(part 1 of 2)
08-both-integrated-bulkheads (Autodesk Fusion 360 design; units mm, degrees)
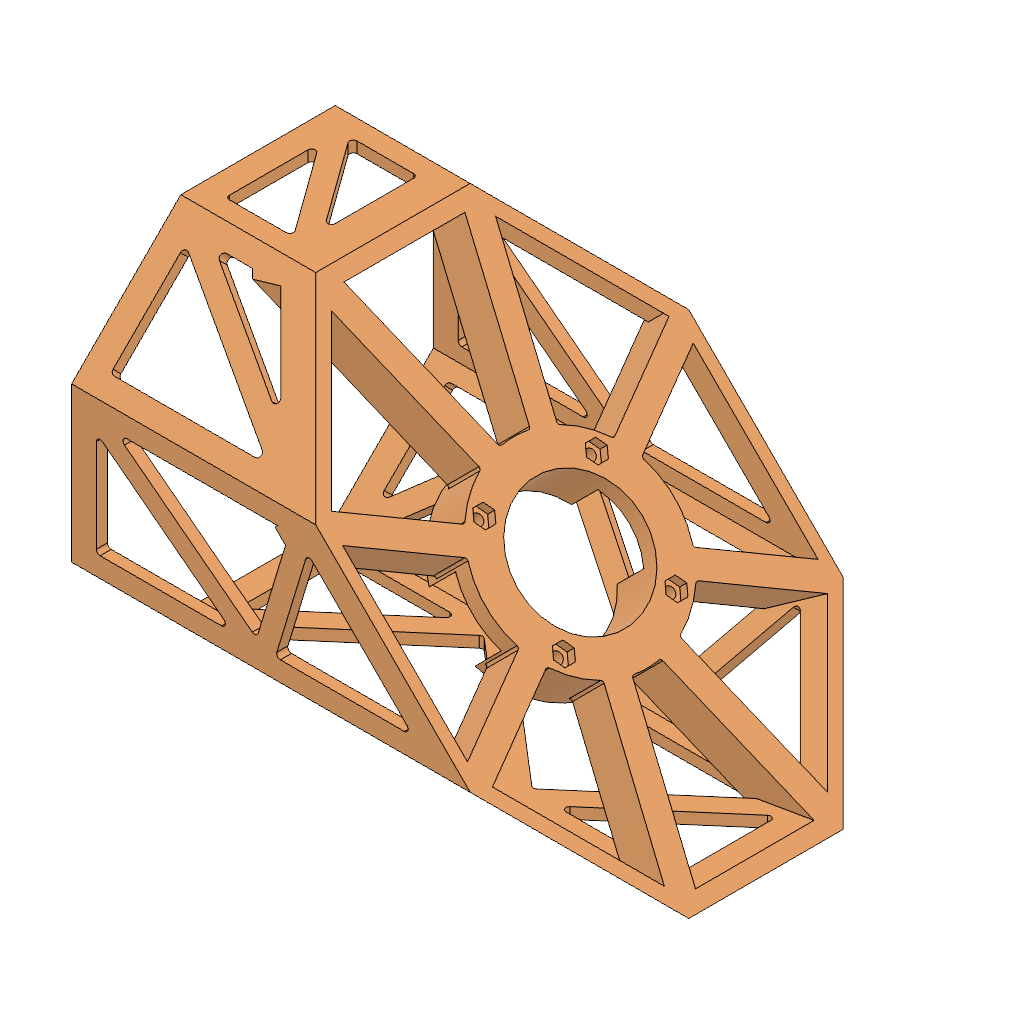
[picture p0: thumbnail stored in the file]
part number: 2026-11-02-20-17-55-344
part number: 2026-11-02-20-17-59-218
part number: 2026-11-02-20-17-59-224
parameter "bodyWidth" = 150 comment "Regular octagon across flats; corner diameter is larger."
parameter "bodyLength" = 260 comment "Overall straight length of the shared master blank."
parameter "splitAngle" = 45 comment "Keep this lesson angle at45 degrees."
parameter "faceGap" = 1 comment "Gap between the two printed joint faces."
parameter "wall" = 4.5 comment "Integrated shell and side brace radial thickness."
parameter "faceHalfWidth" = 31.066 (= "bodyWidth * ( sqrt(2) - 1 ) / 2") comment "Half-width of each outer planar facet."
parameter "memberWidth" = 8 comment "Nominal brace and corner chord width in a facet."
parameter "nodeHalfWidth" = 27.066 (= "faceHalfWidth - memberWidth / 2") comment "Chord centerlines measured from facet center."
parameter "jointNodeQ" = 7 comment "First truss skeleton row from the center joint plane."
parameter "endRim" = 10 comment "Uncut axial rim at each distant end."
parameter "endNodeX" = 124 (= "bodyLength / 2 - endRim + memberWidth / 2") comment "Last skeleton row before aperture inset."
parameter "apertureRadius" = 1.5 comment "Rounded internal corners at triangular openings."
parameter "spokeWidth" = 10 comment "Width of each deep bearing bulkhead spoke."
parameter "spokeDepth" = 18 comment "Bulkhead depth normal to the diagonal joint face."
parameter "carrierOD" = 52 comment "Outside of integrated A front bearing carrier."
parameter "rearCarrierClearance" = 46 comment "Internal carrier relief above front bearing shoulder."
parameter "tubeCornerChamfer" = 0.5 comment "Exposed outside octagon corner bevel."
parameter "tubeRimChamfer" = 0.3 comment "End rim and print-contact edge relief."
parameter "cordStation" = 125 (= "bodyLength / 2 - endRim / 2") comment "Load-test cord port center measured along body X."
parameter "bearingOD" = 22 comment "608 measured outside diameter."
parameter "bearingID" = 8 comment "608 bore."
parameter "bearingWidth" = 7 comment "608 width."
parameter "seatAllowance" = 0.2 comment "Trial DIAMETRAL clearance; choose with printed coupon."
parameter "seatDiameter" = 22.2 (= "bearingOD + seatAllowance") comment "Measured fit controls this."
parameter "coreOD" = 44 comment "Bearing holder outer diameter."
parameter "raceRelief" = 19.5 comment "Outer-ring shoulder opening; verify seals."
parameter "frontSeatDepth" = 7.1 comment "0.1 mm outer-ring axial allowance."
parameter "rearSeatDepth" = 7.2 comment "0.2 mm outer-ring axial float."
parameter "shoulder" = 3 comment "Backing behind each bearing seat."
parameter "supportSpacer" = 12 comment "Purchased metal M3 spacer length."
parameter "supportCircle" = 34 comment "Three M3 support bolts."
parameter "supportSpacerOD" = 6 comment "Purchased spacer outside diameter."
parameter "capThickness" = 3 comment "Both printed outer-ring retaining caps."
parameter "m3Clearance" = 3.3 comment "M3 through holes."
parameter "m4Clearance" = 4.3 comment "M4 through holes."
parameter "qFront" = 0.5 (= "faceGap / 2") comment "Front bearing starts at A mating face."
parameter "qFrontBack" = 10.6 (= "qFront + frontSeatDepth + shoulder") comment "End of integrated A holder."
parameter "qRearBase" = 22.6 (= "qFrontBack + supportSpacer") comment "Start of removable rear holder."
parameter "qRearBearing" = 25.6 (= "qRearBase + shoulder") comment "Rear bearing inner end."
parameter "qRearEnd" = 32.8 (= "qRearBearing + rearSeatDepth") comment "Rear holder outer end."
parameter "bearingSpacing" = 25.1 (= "qRearBearing - qFront") comment "Derived support-center spacing, not a bearing rating."
parameter "mountOD" = 76 comment "B mount and F flange outside diameter."
parameter "mountCircle" = 64 comment "Four M4 attachment holes."
parameter "mountOpening" = 50.3 comment "B through opening."
parameter "hubFace" = -23 comment "Metal hub flat mounting face."
parameter "adapterThickness" = 6 comment "F flange and metal compression sleeve length."
parameter "pilotDiameter" = 50 comment "F shallow centering pilot."
parameter "pilotInside" = 34 comment "Clearance around metal hub."
parameter "pilotHeight" = 2 comment "Short pilot only."
parameter "hubHoleSpacing" = 16 comment "Metal Sonic hub square hole spacing."
parameter "sleeveOD" = 8 comment "M4 metal compression sleeves."
parameter "sleeveAllowance" = 0.2 comment "Trial DIAMETRAL sleeve clearance."
parameter "shaftClearance" = 8.5 comment "F clearance hole; not a bearing."
parameter "nutAF" = 7.2 comment "M4 nominal 7 AF nut trial pocket."
parameter "nutDepth" = 4 comment "Open front M4 nut pocket."
parameter "rootRadius" = 1 comment "Hub-to-wall blend."
parameter "entryChamfer" = 0.4 comment "Assembly lead-in."
parameter "bedRelief" = 0.3 comment "Bed-contact edge allowance."
sketch "01 Master Octagon" plane through (0, 0, 0) normal (1, 0, 0) x axis (0, 0, -1)
  line L1 (31.066, 75) -> (75, 31.066)
  line L2 (-31.066, 75) -> (31.066, 75)
  line L3 (-75, 31.066) -> (-31.066, 75)
  line L4 (-75, -31.066) -> (-75, 31.066)
  line L5 (-31.066, -75) -> (-75, -31.066)
  line L6 (31.066, -75) -> (-31.066, -75)
  line L7 (75, -31.066) -> (31.066, -75)
  line L8 (75, 31.066) -> (75, -31.066)
  point P1 (0, 0)
  point P10 (0, 0)
  point P3 (31.066, 75)
  point P8 (31.066, -75)
  coincident P1 P10
  horizontal L2
  dimension "d59" distance P3 P8 = 150 (= "bodyWidth")
extrude "Extrude1" new body sketch "01 Master Octagon" distance 260 (= "bodyLength")
work_plane "WorkPlane1" RotateAngle 45 (= "splitAngle") ExtraOffset 0
split "Split1"
offset_faces "OffsetFaces1" distance -0.5 (= "-faceGap / 2")
offset_faces "OffsetFaces2" distance -0.5 (= "-faceGap / 2")
component_from_bodies "Body->Comp1"
component_from_bodies "Body->Comp2"
shell "Shell1" innerThickness 4.5 (= "wall")
shell "Shell1" innerThickness 4.5 (= "wall")
work_plane "WorkPlane1" RotateAngle -90 ExtraOffset 0
work_plane "WorkPlane2" AlongDistance 75 (= "bodyWidth / 2") ExtraOffset 0
sketch "A Facet 0 Triangle 1" plane through (0, 75, 0) normal (0, 1, 0) x axis (1, 0, 0)
  line L1 (-65.1005, -27.066) -> (-65.1005, 27.066)
  line L2 (60.9665, 27.066) -> (-65.1005, -27.066)
  line L3 (-65.1005, 27.066) -> (60.9665, 27.066)
  line L4 (-61.1005, -20.9953) -> (-61.1005, 23.066)
  line L5 (41.513, 23.066) -> (-61.1005, -20.9953)
  line L6 (-61.1005, 23.066) -> (41.513, 23.066)
  point P1 (0, 0)
  point P2 (-65.1005, 27.066)
  point P3 (-65.1005, -27.066)
  point P4 (60.9665, 27.066)
  dimension "d72" distance P1 P2 = 65.1005 (= "Linear Dimension-2")
  dimension "d73" distance P1 P2 = 27.066 (= "Linear Dimension-3")
  dimension "d74" distance P1 P3 = 65.1005 (= "Linear Dimension-4")
  dimension "d75" distance P1 P3 = 27.066 (= "Linear Dimension-5")
  dimension "d76" distance P1 P4 = 60.9665 (= "Linear Dimension-6")
  dimension "d77" distance P1 P4 = 27.066 (= "Linear Dimension-7")
  dimension "d78" = -4 (= "-memberWidth / 2")
extrude "Extrude1" cut sketch "A Facet 0 Triangle 1" profile of L5 L6 L4 against normal blind 4.7 (magnitude of "-( wall + 0.2 mm )")
sketch "A Facet 0 Triangle 2" plane through (0, 75, 0) normal (0, 1, 0) x axis (1, 0, 0)
  line L1 (60.9665, 27.066) -> (-65.1005, -27.066)
  line L2 (92.4832, -27.066) -> (60.9665, 27.066)
  line L3 (-65.1005, -27.066) -> (92.4832, -27.066)
  line L4 (59.2912, 21.9935) -> (-45.647, -23.066)
  line L5 (85.5258, -23.066) -> (59.2912, 21.9935)
  line L6 (-45.647, -23.066) -> (85.5258, -23.066)
  point P1 (0, 0)
  point P2 (-65.1005, -27.066)
  point P3 (60.9665, 27.066)
  point P4 (92.4832, -27.066)
  dimension "d81" distance P1 P2 = 65.1005 (= "Linear Dimension-2")
  dimension "d82" distance P1 P2 = 27.066 (= "Linear Dimension-3")
  dimension "d83" distance P1 P3 = 60.9665 (= "Linear Dimension-4")
  dimension "d84" distance P1 P3 = 27.066 (= "Linear Dimension-5")
  dimension "d85" distance P1 P4 = 92.4832 (= "Linear Dimension-6")
  dimension "d86" distance P1 P4 = 27.066 (= "Linear Dimension-7")
  dimension "d87" = 4 (= "memberWidth / 2")
extrude "Extrude2" cut sketch "A Facet 0 Triangle 2" profile of L5 L6 L4 against normal blind 4.7 (magnitude of "-( wall + 0.2 mm )")
sketch "A Facet 0 Triangle 3" plane through (0, 75, 0) normal (0, 1, 0) x axis (1, 0, 0)
  line L1 (92.4832, -27.066) -> (60.9665, 27.066)
  line L2 (124, 27.066) -> (92.4832, -27.066)
  line L3 (60.9665, 27.066) -> (124, 27.066)
  line L4 (92.4832, -19.1161) -> (67.924, 23.066)
  line L5 (117.0425, 23.066) -> (92.4832, -19.1161)
  line L6 (67.924, 23.066) -> (117.0425, 23.066)
  point P1 (0, 0)
  point P2 (60.9665, 27.066)
  point P3 (92.4832, -27.066)
  point P4 (124, 27.066)
  dimension "d90" distance P1 P2 = 60.9665 (= "Linear Dimension-2")
  dimension "d91" distance P1 P2 = 27.066 (= "Linear Dimension-3")
  dimension "d92" distance P1 P3 = 92.4832 (= "Linear Dimension-4")
  dimension "d93" distance P1 P3 = 27.066 (= "Linear Dimension-5")
  dimension "d94" distance P1 P4 = 124 (= "Linear Dimension-6")
  dimension "d95" distance P1 P4 = 27.066 (= "Linear Dimension-7")
  dimension "d96" = -4 (= "-memberWidth / 2")
extrude "Extrude3" cut sketch "A Facet 0 Triangle 3" profile of L5 L6 L4 against normal blind 4.7 (magnitude of "-( wall + 0.2 mm )")
sketch "A Facet 0 Triangle 4" plane through (0, 75, 0) normal (0, 1, 0) x axis (1, 0, 0)
  line L1 (124, 27.066) -> (92.4832, -27.066)
  line L2 (124, -27.066) -> (124, 27.066)
  line L3 (92.4832, -27.066) -> (124, -27.066)
  line L4 (120, 12.2459) -> (99.4407, -23.066)
  line L5 (120, -23.066) -> (120, 12.2459)
  line L6 (99.4407, -23.066) -> (120, -23.066)
  point P1 (0, 0)
  point P2 (92.4832, -27.066)
  point P3 (124, 27.066)
  point P4 (124, -27.066)
  dimension "d99" distance P1 P2 = 92.4832 (= "Linear Dimension-2")
  dimension "d100" distance P1 P2 = 27.066 (= "Linear Dimension-3")
  dimension "d101" distance P1 P3 = 124 (= "Linear Dimension-4")
  dimension "d102" distance P1 P3 = 27.066 (= "Linear Dimension-5")
  dimension "d103" distance P1 P4 = 124 (= "Linear Dimension-6")
  dimension "d104" distance P1 P4 = 27.066 (= "Linear Dimension-7")
  dimension "d105" = 4 (= "memberWidth / 2")
extrude "Extrude4" cut sketch "A Facet 0 Triangle 4" profile of L5 L6 L4 against normal blind 4.7 (magnitude of "-( wall + 0.2 mm )")
fillet "Fillet1" radius 1.5 (= "apertureRadius")
work_plane "WorkPlane3" RotateAngle -45 ExtraOffset 0
work_plane "WorkPlane4" AlongDistance 75 (= "bodyWidth / 2") ExtraOffset 0
sketch "A Facet 45 Triangle 1" plane through (0, 53.033, 53.033) normal (0, 0.7071, 0.7071) x axis (1, 0, 0)
  line L1 (-23.9949, -27.066) -> (-62.2721, 27.066)
  line L2 (-0.1814, 27.066) -> (-23.9949, -27.066)
  line L3 (-62.2721, 27.066) -> (-0.1814, 27.066)
  line L4 (-24.81, -18.9852) -> (-54.5447, 23.066)
  line L5 (-6.311, 23.066) -> (-24.81, -18.9852)
  line L6 (-54.5447, 23.066) -> (-6.311, 23.066)
  point P1 (0, 0)
  point P2 (-62.2721, 27.066)
  point P3 (-23.9949, -27.066)
  point P4 (-0.1814, 27.066)
  dimension "d114" distance P1 P2 = 62.2721 (= "Linear Dimension-2")
  dimension "d115" distance P1 P2 = 27.066 (= "Linear Dimension-3")
  dimension "d116" distance P1 P3 = 23.9949 (= "Linear Dimension-4")
  dimension "d117" distance P1 P3 = 27.066 (= "Linear Dimension-5")
  dimension "d118" distance P1 P4 = 0.1814 (= "Linear Dimension-6")
  dimension "d119" distance P1 P4 = 27.066 (= "Linear Dimension-7")
  dimension "d120" = -4 (= "-memberWidth / 2")
extrude "Extrude5" cut sketch "A Facet 45 Triangle 1" profile of L5 L6 L4 against normal blind 4.7 (magnitude of "-( wall + 0.2 mm )")
sketch "A Facet 45 Triangle 2" plane through (0, 53.033, 53.033) normal (0, 0.7071, 0.7071) x axis (1, 0, 0)
  line L1 (-0.1814, 27.066) -> (-23.9949, -27.066)
  line L2 (74.6684, -27.066) -> (-0.1814, 27.066)
  line L3 (-23.9949, -27.066) -> (74.6684, -27.066)
  line L4 (1.4863, 20.9235) -> (-17.8653, -23.066)
  line L5 (62.3117, -23.066) -> (1.4863, 20.9235)
  line L6 (-17.8653, -23.066) -> (62.3117, -23.066)
  point P1 (0, 0)
  point P2 (-23.9949, -27.066)
  point P3 (-0.1814, 27.066)
  point P4 (74.6684, -27.066)
  dimension "d123" distance P1 P2 = 23.9949 (= "Linear Dimension-2")
  dimension "d124" distance P1 P2 = 27.066 (= "Linear Dimension-3")
  dimension "d125" distance P1 P3 = 0.1814 (= "Linear Dimension-4")
  dimension "d126" distance P1 P3 = 27.066 (= "Linear Dimension-5")
  dimension "d127" distance P1 P4 = 74.6684 (= "Linear Dimension-6")
  dimension "d128" distance P1 P4 = 27.066 (= "Linear Dimension-7")
  dimension "d129" = 4 (= "memberWidth / 2")
extrude "Extrude6" cut sketch "A Facet 45 Triangle 2" profile of L5 L6 L4 against normal blind 4.7 (magnitude of "-( wall + 0.2 mm )")
sketch "A Facet 45 Triangle 3" plane through (0, 53.033, 53.033) normal (0, 0.7071, 0.7071) x axis (1, 0, 0)
  line L1 (74.6684, -27.066) -> (-0.1814, 27.066)
  line L2 (124, 27.066) -> (74.6684, -27.066)
  line L3 (-0.1814, 27.066) -> (124, 27.066)
  line L4 (74.1179, -21.7315) -> (12.1753, 23.066)
  line L5 (114.9429, 23.066) -> (74.1179, -21.7315)
  line L6 (12.1753, 23.066) -> (114.9429, 23.066)
  point P1 (0, 0)
  point P2 (-0.1814, 27.066)
  point P3 (74.6684, -27.066)
  point P4 (124, 27.066)
  dimension "d132" distance P1 P2 = 0.1814 (= "Linear Dimension-2")
  dimension "d133" distance P1 P2 = 27.066 (= "Linear Dimension-3")
  dimension "d134" distance P1 P3 = 74.6684 (= "Linear Dimension-4")
  dimension "d135" distance P1 P3 = 27.066 (= "Linear Dimension-5")
  dimension "d136" distance P1 P4 = 124 (= "Linear Dimension-6")
  dimension "d137" distance P1 P4 = 27.066 (= "Linear Dimension-7")
  dimension "d138" = -4 (= "-memberWidth / 2")
extrude "Extrude7" cut sketch "A Facet 45 Triangle 3" profile of L5 L6 L4 against normal blind 4.7 (magnitude of "-( wall + 0.2 mm )")
sketch "A Facet 45 Triangle 4" plane through (0, 53.033, 53.033) normal (0, 0.7071, 0.7071) x axis (1, 0, 0)
  line L1 (124, 27.066) -> (74.6684, -27.066)
  line L2 (124, -27.066) -> (124, 27.066)
  line L3 (74.6684, -27.066) -> (124, -27.066)
  line L4 (120, 16.7383) -> (83.7255, -23.066)
  line L5 (120, -23.066) -> (120, 16.7383)
  line L6 (83.7255, -23.066) -> (120, -23.066)
  point P1 (0, 0)
  point P2 (74.6684, -27.066)
  point P3 (124, 27.066)
  point P4 (124, -27.066)
  dimension "d141" distance P1 P2 = 74.6684 (= "Linear Dimension-2")
  dimension "d142" distance P1 P2 = 27.066 (= "Linear Dimension-3")
  dimension "d143" distance P1 P3 = 124 (= "Linear Dimension-4")
  dimension "d144" distance P1 P3 = 27.066 (= "Linear Dimension-5")
  dimension "d145" distance P1 P4 = 124 (= "Linear Dimension-6")
  dimension "d146" distance P1 P4 = 27.066 (= "Linear Dimension-7")
  dimension "d147" = 4 (= "memberWidth / 2")
extrude "Extrude8" cut sketch "A Facet 45 Triangle 4" profile of L5 L6 L4 against normal blind 4.7 (magnitude of "-( wall + 0.2 mm )")
fillet "Fillet2" radius 1.5 (= "apertureRadius")
work_plane "WorkPlane5" RotateAngle 0 ExtraOffset 0
work_plane "WorkPlane6" AlongDistance 75 (= "bodyWidth / 2") ExtraOffset 0
sketch "A Facet 90 Triangle 1" plane through (0, 0, 75) normal (0, 0, 1) x axis (1, 0, 0)
  line L1 (36.9655, -27.066) -> (-17.1665, 27.066)
  line L2 (53.4167, 27.066) -> (36.9655, -27.066)
  line L3 (-17.1665, 27.066) -> (53.4167, 27.066)
  line L4 (35.0777, -19.5214) -> (-7.5097, 23.066)
  line L5 (48.0205, 23.066) -> (35.0777, -19.5214)
  line L6 (-7.5097, 23.066) -> (48.0205, 23.066)
  point P1 (0, 0)
  point P2 (-17.1665, 27.066)
  point P3 (36.9655, -27.066)
  point P4 (53.4167, 27.066)
  dimension "d156" distance P1 P2 = 17.1665 (= "Linear Dimension-2")
  dimension "d157" distance P1 P2 = 27.066 (= "Linear Dimension-3")
  dimension "d158" distance P1 P3 = 36.9655 (= "Linear Dimension-4")
  dimension "d159" distance P1 P3 = 27.066 (= "Linear Dimension-5")
  dimension "d160" distance P1 P4 = 53.4167 (= "Linear Dimension-6")
  dimension "d161" distance P1 P4 = 27.066 (= "Linear Dimension-7")
  dimension "d162" = -4 (= "-memberWidth / 2")
extrude "Extrude9" cut sketch "A Facet 90 Triangle 1" profile of L5 L6 L4 against normal blind 4.7 (magnitude of "-( wall + 0.2 mm )")
sketch "A Facet 90 Triangle 2" plane through (0, 0, 75) normal (0, 0, 1) x axis (1, 0, 0)
  line L1 (53.4167, 27.066) -> (36.9655, -27.066)
  line L2 (124, -27.066) -> (53.4167, 27.066)
  line L3 (36.9655, -27.066) -> (124, -27.066)
  line L4 (55.5648, 20.3777) -> (42.3618, -23.066)
  line L5 (112.2115, -23.066) -> (55.5648, 20.3777)
  line L6 (42.3618, -23.066) -> (112.2115, -23.066)
  point P1 (0, 0)
  point P2 (36.9655, -27.066)
  point P3 (53.4167, 27.066)
  point P4 (124, -27.066)
  dimension "d165" distance P1 P2 = 36.9655 (= "Linear Dimension-2")
  dimension "d166" distance P1 P2 = 27.066 (= "Linear Dimension-3")
  dimension "d167" distance P1 P3 = 53.4167 (= "Linear Dimension-4")
  dimension "d168" distance P1 P3 = 27.066 (= "Linear Dimension-5")
  dimension "d169" distance P1 P4 = 124 (= "Linear Dimension-6")
  dimension "d170" distance P1 P4 = 27.066 (= "Linear Dimension-7")
  dimension "d171" = 4 (= "memberWidth / 2")
extrude "Extrude10" cut sketch "A Facet 90 Triangle 2" profile of L5 L6 L4 against normal blind 4.7 (magnitude of "-( wall + 0.2 mm )")
sketch "A Facet 90 Triangle 3" plane through (0, 0, 75) normal (0, 0, 1) x axis (1, 0, 0)
  line L1 (124, -27.066) -> (53.4167, 27.066)
  line L2 (124, 27.066) -> (124, -27.066)
  line L3 (53.4167, 27.066) -> (124, 27.066)
  line L4 (120, -18.9574) -> (65.2053, 23.066)
  line L5 (120, 23.066) -> (120, -18.9574)
  line L6 (65.2053, 23.066) -> (120, 23.066)
  point P1 (0, 0)
  point P2 (53.4167, 27.066)
  point P3 (124, -27.066)
  point P4 (124, 27.066)
  dimension "d174" distance P1 P2 = 53.4167 (= "Linear Dimension-2")
  dimension "d175" distance P1 P2 = 27.066 (= "Linear Dimension-3")
  dimension "d176" distance P1 P3 = 124 (= "Linear Dimension-4")
  dimension "d177" distance P1 P3 = 27.066 (= "Linear Dimension-5")
  dimension "d178" distance P1 P4 = 124 (= "Linear Dimension-6")
  dimension "d179" distance P1 P4 = 27.066 (= "Linear Dimension-7")
  dimension "d180" = -4 (= "-memberWidth / 2")
extrude "Extrude11" cut sketch "A Facet 90 Triangle 3" profile of L5 L6 L4 against normal blind 4.7 (magnitude of "-( wall + 0.2 mm )")
fillet "Fillet3" radius 1.5 (= "apertureRadius")
work_plane "WorkPlane7" RotateAngle 45 ExtraOffset 0
work_plane "WorkPlane8" AlongDistance 75 (= "bodyWidth / 2") ExtraOffset 0
sketch "A Facet 135 Triangle 1" plane through (0, -53.033, 53.033) normal (0, -0.7071, 0.7071) x axis (1, 0, 0)
  line L1 (82.0711, -27.066) -> (43.7939, 27.066)
  line L2 (124, 27.066) -> (82.0711, -27.066)
  line L3 (43.7939, 27.066) -> (124, 27.066)
  line L4 (82.2175, -20.3449) -> (51.5213, 23.066)
  line L5 (115.8422, 23.066) -> (82.2175, -20.3449)
  line L6 (51.5213, 23.066) -> (115.8422, 23.066)
  point P1 (0, 0)
  point P2 (43.7939, 27.066)
  point P3 (82.0711, -27.066)
  point P4 (124, 27.066)
  dimension "d189" distance P1 P2 = 43.7939 (= "Linear Dimension-2")
  dimension "d190" distance P1 P2 = 27.066 (= "Linear Dimension-3")
  dimension "d191" distance P1 P3 = 82.0711 (= "Linear Dimension-4")
  dimension "d192" distance P1 P3 = 27.066 (= "Linear Dimension-5")
  dimension "d193" distance P1 P4 = 124 (= "Linear Dimension-6")
  dimension "d194" distance P1 P4 = 27.066 (= "Linear Dimension-7")
  dimension "d195" = -4 (= "-memberWidth / 2")
extrude "Extrude12" cut sketch "A Facet 135 Triangle 1" profile of L5 L6 L4 against normal blind 4.7 (magnitude of "-( wall + 0.2 mm )")
sketch "A Facet 135 Triangle 2" plane through (0, -53.033, 53.033) normal (0, -0.7071, 0.7071) x axis (1, 0, 0)
  line L1 (124, 27.066) -> (82.0711, -27.066)
  line L2 (124, -27.066) -> (124, 27.066)
  line L3 (82.0711, -27.066) -> (124, -27.066)
  line L4 (120, 15.3697) -> (90.2289, -23.066)
  line L5 (120, -23.066) -> (120, 15.3697)
  line L6 (90.2289, -23.066) -> (120, -23.066)
  point P1 (0, 0)
  point P2 (82.0711, -27.066)
  point P3 (124, 27.066)
  point P4 (124, -27.066)
  dimension "d198" distance P1 P2 = 82.0711 (= "Linear Dimension-2")
  dimension "d199" distance P1 P2 = 27.066 (= "Linear Dimension-3")
  dimension "d200" distance P1 P3 = 124 (= "Linear Dimension-4")
  dimension "d201" distance P1 P3 = 27.066 (= "Linear Dimension-5")
  dimension "d202" distance P1 P4 = 124 (= "Linear Dimension-6")
  dimension "d203" distance P1 P4 = 27.066 (= "Linear Dimension-7")
  dimension "d204" = 4 (= "memberWidth / 2")
extrude "Extrude13" cut sketch "A Facet 135 Triangle 2" profile of L5 L6 L4 against normal blind 4.7 (magnitude of "-( wall + 0.2 mm )")
fillet "Fillet4" radius 1.5 (= "apertureRadius")
work_plane "WorkPlane9" RotateAngle 90 ExtraOffset 0
work_plane "WorkPlane10" AlongDistance 75 (= "bodyWidth / 2") ExtraOffset 0
sketch "A Facet 180 Triangle 1" plane through (0, -75, 0) normal (0, -1, 0) x axis (-1, 0, 0)
  line L1 (-84.8995, 27.066) -> (-84.8995, -27.066)
  line L2 (-124, -27.066) -> (-84.8995, 27.066)
  line L3 (-84.8995, -27.066) -> (-124, -27.066)
  line L4 (-88.8995, 14.697) -> (-88.8995, -23.066)
  line L5 (-116.1764, -23.066) -> (-88.8995, 14.697)
  line L6 (-88.8995, -23.066) -> (-116.1764, -23.066)
  point P1 (0, 0)
  point P2 (-84.8995, -27.066)
  point P3 (-84.8995, 27.066)
  point P4 (-124, -27.066)
  dimension "d213" distance P1 P2 = 84.8995 (= "Linear Dimension-2")
  dimension "d214" distance P1 P2 = 27.066 (= "Linear Dimension-3")
  dimension "d215" distance P1 P3 = 84.8995 (= "Linear Dimension-4")
  dimension "d216" distance P1 P3 = 27.066 (= "Linear Dimension-5")
  dimension "d217" distance P1 P4 = 124 (= "Linear Dimension-6")
  dimension "d218" distance P1 P4 = 27.066 (= "Linear Dimension-7")
  dimension "d219" = -4 (= "-memberWidth / 2")
extrude "Extrude14" cut sketch "A Facet 180 Triangle 1" profile of L5 L6 L4 against normal blind 4.7 (magnitude of "-( wall + 0.2 mm )")
sketch "A Facet 180 Triangle 2" plane through (0, -75, 0) normal (0, -1, 0) x axis (-1, 0, 0)
  line L1 (-124, -27.066) -> (-84.8995, 27.066)
  line L2 (-124, 27.066) -> (-124, -27.066)
  line L3 (-84.8995, 27.066) -> (-124, 27.066)
  line L4 (-120, -14.697) -> (-92.7231, 23.066)
  line L5 (-120, 23.066) -> (-120, -14.697)
  line L6 (-92.7231, 23.066) -> (-120, 23.066)
  point P1 (0, 0)
  point P2 (-84.8995, 27.066)
  point P3 (-124, -27.066)
  point P4 (-124, 27.066)
  dimension "d222" distance P1 P2 = 84.8995 (= "Linear Dimension-2")
  dimension "d223" distance P1 P2 = 27.066 (= "Linear Dimension-3")
  dimension "d224" distance P1 P3 = 124 (= "Linear Dimension-4")
  dimension "d225" distance P1 P3 = 27.066 (= "Linear Dimension-5")
  dimension "d226" distance P1 P4 = 124 (= "Linear Dimension-6")
  dimension "d227" distance P1 P4 = 27.066 (= "Linear Dimension-7")
  dimension "d228" = 4 (= "memberWidth / 2")
extrude "Extrude15" cut sketch "A Facet 180 Triangle 2" profile of L5 L6 L4 against normal blind 4.7 (magnitude of "-( wall + 0.2 mm )")
fillet "Fillet5" radius 1.5 (= "apertureRadius")
work_plane "WorkPlane11" RotateAngle 135 ExtraOffset 0
work_plane "WorkPlane12" AlongDistance 75 (= "bodyWidth / 2") ExtraOffset 0
sketch "A Facet 225 Triangle 1" plane through (0, -53.033, -53.033) normal (0, -0.7071, -0.7071) x axis (1, 0, 0)
  line L1 (43.7939, -27.066) -> (82.0711, 27.066)
  line L2 (124, 27.066) -> (43.7939, -27.066)
  line L3 (82.0711, 27.066) -> (124, 27.066)
  line L4 (59.6927, -11.51) -> (84.1416, 23.066)
  line L5 (110.9231, 23.066) -> (59.6927, -11.51)
  line L6 (84.1416, 23.066) -> (110.9231, 23.066)
  point P1 (0, 0)
  point P2 (82.0711, 27.066)
  point P3 (43.7939, -27.066)
  point P4 (124, 27.066)
  dimension "d237" distance P1 P2 = 82.0711 (= "Linear Dimension-2")
  dimension "d238" distance P1 P2 = 27.066 (= "Linear Dimension-3")
  dimension "d239" distance P1 P3 = 43.7939 (= "Linear Dimension-4")
  dimension "d240" distance P1 P3 = 27.066 (= "Linear Dimension-5")
  dimension "d241" distance P1 P4 = 124 (= "Linear Dimension-6")
  dimension "d242" distance P1 P4 = 27.066 (= "Linear Dimension-7")
  dimension "d243" = -4 (= "-memberWidth / 2")
extrude "Extrude16" cut sketch "A Facet 225 Triangle 1" profile of L5 L6 L4 against normal blind 4.7 (magnitude of "-( wall + 0.2 mm )")
sketch "A Facet 225 Triangle 2" plane through (0, -53.033, -53.033) normal (0, -0.7071, -0.7071) x axis (1, 0, 0)
  line L1 (124, 27.066) -> (43.7939, -27.066)
  line L2 (124, -27.066) -> (124, 27.066)
  line L3 (43.7939, -27.066) -> (124, -27.066)
  line L4 (120, 19.5406) -> (56.8709, -23.066)
  line L5 (120, -23.066) -> (120, 19.5406)
  line L6 (56.8709, -23.066) -> (120, -23.066)
  point P1 (0, 0)
  point P2 (43.7939, -27.066)
  point P3 (124, 27.066)
  point P4 (124, -27.066)
  dimension "d246" distance P1 P2 = 43.7939 (= "Linear Dimension-2")
  dimension "d247" distance P1 P2 = 27.066 (= "Linear Dimension-3")
  dimension "d248" distance P1 P3 = 124 (= "Linear Dimension-4")
  dimension "d249" distance P1 P3 = 27.066 (= "Linear Dimension-5")
  dimension "d250" distance P1 P4 = 124 (= "Linear Dimension-6")
  dimension "d251" distance P1 P4 = 27.066 (= "Linear Dimension-7")
  dimension "d252" = 4 (= "memberWidth / 2")
extrude "Extrude17" cut sketch "A Facet 225 Triangle 2" profile of L5 L6 L4 against normal blind 4.7 (magnitude of "-( wall + 0.2 mm )")
fillet "Fillet6" radius 1.5 (= "apertureRadius")
work_plane "WorkPlane13" RotateAngle 180 ExtraOffset 0
work_plane "WorkPlane14" AlongDistance 75 (= "bodyWidth / 2") ExtraOffset 0
sketch "A Facet 270 Triangle 1" plane through (0, 0, -75) normal (0, 0, -1) x axis (-1, 0, 0)
  line L1 (17.1665, 27.066) -> (-36.9655, -27.066)
  line L2 (-80.4828, -27.066) -> (17.1665, 27.066)
  line L3 (-36.9655, -27.066) -> (-80.4828, -27.066)
  line L4 (-5.7896, 9.7668) -> (-38.6224, -23.066)
  line L5 (-65.0169, -23.066) -> (-5.7896, 9.7668)
  line L6 (-38.6224, -23.066) -> (-65.0169, -23.066)
  point P1 (0, 0)
  point P2 (-36.9655, -27.066)
  point P3 (17.1665, 27.066)
  point P4 (-80.4828, -27.066)
  dimension "d261" distance P1 P2 = 36.9655 (= "Linear Dimension-2")
  dimension "d262" distance P1 P2 = 27.066 (= "Linear Dimension-3")
  dimension "d263" distance P1 P3 = 17.1665 (= "Linear Dimension-4")
  dimension "d264" distance P1 P3 = 27.066 (= "Linear Dimension-5")
  dimension "d265" distance P1 P4 = 80.4828 (= "Linear Dimension-6")
  dimension "d266" distance P1 P4 = 27.066 (= "Linear Dimension-7")
  dimension "d267" = -4 (= "-memberWidth / 2")
extrude "Extrude18" cut sketch "A Facet 270 Triangle 1" profile of L5 L6 L4 against normal blind 4.7 (magnitude of "-( wall + 0.2 mm )")
sketch "A Facet 270 Triangle 2" plane through (0, 0, -75) normal (0, 0, -1) x axis (-1, 0, 0)
  line L1 (-80.4828, -27.066) -> (17.1665, 27.066)
  line L2 (-124, 27.066) -> (-80.4828, -27.066)
  line L3 (17.1665, 27.066) -> (-124, 27.066)
  line L4 (-79.4759, -21.9343) -> (1.7007, 23.066)
  line L5 (-115.6521, 23.066) -> (-79.4759, -21.9343)
  line L6 (1.7007, 23.066) -> (-115.6521, 23.066)
  point P1 (0, 0)
  point P2 (17.1665, 27.066)
  point P3 (-80.4828, -27.066)
  point P4 (-124, 27.066)
  dimension "d270" distance P1 P2 = 17.1665 (= "Linear Dimension-2")
  dimension "d271" distance P1 P2 = 27.066 (= "Linear Dimension-3")
  dimension "d272" distance P1 P3 = 80.4828 (= "Linear Dimension-4")
  dimension "d273" distance P1 P3 = 27.066 (= "Linear Dimension-5")
  dimension "d274" distance P1 P4 = 124 (= "Linear Dimension-6")
  dimension "d275" distance P1 P4 = 27.066 (= "Linear Dimension-7")
  dimension "d276" = 4 (= "memberWidth / 2")
extrude "Extrude19" cut sketch "A Facet 270 Triangle 2" profile of L5 L6 L4 against normal blind 4.7 (magnitude of "-( wall + 0.2 mm )")
sketch "A Facet 270 Triangle 3" plane through (0, 0, -75) normal (0, 0, -1) x axis (-1, 0, 0)
  line L1 (-124, 27.066) -> (-80.4828, -27.066)
  line L2 (-124, -27.066) -> (-124, 27.066)
  line L3 (-80.4828, -27.066) -> (-124, -27.066)
  line L4 (-120, 15.7062) -> (-88.8307, -23.066)
  line L5 (-120, -23.066) -> (-120, 15.7062)
  line L6 (-88.8307, -23.066) -> (-120, -23.066)
  point P1 (0, 0)
  point P2 (-80.4828, -27.066)
  point P3 (-124, 27.066)
  point P4 (-124, -27.066)
  dimension "d279" distance P1 P2 = 80.4828 (= "Linear Dimension-2")
  dimension "d280" distance P1 P2 = 27.066 (= "Linear Dimension-3")
  dimension "d281" distance P1 P3 = 124 (= "Linear Dimension-4")
  dimension "d282" distance P1 P3 = 27.066 (= "Linear Dimension-5")
  dimension "d283" distance P1 P4 = 124 (= "Linear Dimension-6")
  dimension "d284" distance P1 P4 = 27.066 (= "Linear Dimension-7")
  dimension "d285" = -4 (= "-memberWidth / 2")
extrude "Extrude20" cut sketch "A Facet 270 Triangle 3" profile of L5 L6 L4 against normal blind 4.7 (magnitude of "-( wall + 0.2 mm )")
fillet "Fillet7" radius 1.5 (= "apertureRadius")
work_plane "WorkPlane15" RotateAngle 225 ExtraOffset 0
work_plane "WorkPlane16" AlongDistance 75 (= "bodyWidth / 2") ExtraOffset 0
sketch "A Facet 315 Triangle 1" plane through (0, 53.033, -53.033) normal (0, 0.7071, -0.7071) x axis (1, 0, 0)
  line L1 (-62.2721, -27.066) -> (-23.9949, 27.066)
  line L2 (25.3367, 27.066) -> (-62.2721, -27.066)
  line L3 (-23.9949, 27.066) -> (25.3367, 27.066)
  line L4 (-47.6674, -13.34) -> (-21.9244, 23.066)
  line L5 (11.2532, 23.066) -> (-47.6674, -13.34)
  line L6 (-21.9244, 23.066) -> (11.2532, 23.066)
  point P1 (0, 0)
  point P2 (-23.9949, 27.066)
  point P3 (-62.2721, -27.066)
  point P4 (25.3367, 27.066)
  dimension "d294" distance P1 P2 = 23.9949 (= "Linear Dimension-2")
  dimension "d295" distance P1 P2 = 27.066 (= "Linear Dimension-3")
  dimension "d296" distance P1 P3 = 62.2721 (= "Linear Dimension-4")
  dimension "d297" distance P1 P3 = 27.066 (= "Linear Dimension-5")
  dimension "d298" distance P1 P4 = 25.3367 (= "Linear Dimension-6")
  dimension "d299" distance P1 P4 = 27.066 (= "Linear Dimension-7")
  dimension "d300" = -4 (= "-memberWidth / 2")
extrude "Extrude21" cut sketch "A Facet 315 Triangle 1" profile of L5 L6 L4 against normal blind 4.7 (magnitude of "-( wall + 0.2 mm )")
sketch "A Facet 315 Triangle 2" plane through (0, 53.033, -53.033) normal (0, 0.7071, -0.7071) x axis (1, 0, 0)
  line L1 (25.3367, 27.066) -> (-62.2721, -27.066)
  line L2 (61.9093, -27.066) -> (25.3367, 27.066)
  line L3 (-62.2721, -27.066) -> (61.9093, -27.066)
  line L4 (24.1722, 21.6445) -> (-48.1886, -23.066)
  line L5 (54.3795, -23.066) -> (24.1722, 21.6445)
  line L6 (-48.1886, -23.066) -> (54.3795, -23.066)
  point P1 (0, 0)
  point P2 (-62.2721, -27.066)
  point P3 (25.3367, 27.066)
  point P4 (61.9093, -27.066)
  dimension "d303" distance P1 P2 = 62.2721 (= "Linear Dimension-2")
  dimension "d304" distance P1 P2 = 27.066 (= "Linear Dimension-3")
  dimension "d305" distance P1 P3 = 25.3367 (= "Linear Dimension-4")
  dimension "d306" distance P1 P3 = 27.066 (= "Linear Dimension-5")
  dimension "d307" distance P1 P4 = 61.9093 (= "Linear Dimension-6")
  dimension "d308" distance P1 P4 = 27.066 (= "Linear Dimension-7")
  dimension "d309" = 4 (= "memberWidth / 2")
extrude "Extrude22" cut sketch "A Facet 315 Triangle 2" profile of L5 L6 L4 against normal blind 4.7 (magnitude of "-( wall + 0.2 mm )")
sketch "A Facet 315 Triangle 3" plane through (0, 53.033, -53.033) normal (0, 0.7071, -0.7071) x axis (1, 0, 0)
  line L1 (61.9093, -27.066) -> (25.3367, 27.066)
  line L2 (124, 27.066) -> (61.9093, -27.066)
  line L3 (25.3367, 27.066) -> (124, 27.066)
  line L4 (62.6909, -21.0779) -> (32.8665, 23.066)
  line L5 (113.325, 23.066) -> (62.6909, -21.0779)
  line L6 (32.8665, 23.066) -> (113.325, 23.066)
  point P1 (0, 0)
  point P2 (25.3367, 27.066)
  point P3 (61.9093, -27.066)
  point P4 (124, 27.066)
  dimension "d312" distance P1 P2 = 25.3367 (= "Linear Dimension-2")
  dimension "d313" distance P1 P2 = 27.066 (= "Linear Dimension-3")
  dimension "d314" distance P1 P3 = 61.9093 (= "Linear Dimension-4")
  dimension "d315" distance P1 P3 = 27.066 (= "Linear Dimension-5")
  dimension "d316" distance P1 P4 = 124 (= "Linear Dimension-6")
  dimension "d317" distance P1 P4 = 27.066 (= "Linear Dimension-7")
  dimension "d318" = -4 (= "-memberWidth / 2")
extrude "Extrude23" cut sketch "A Facet 315 Triangle 3" profile of L5 L6 L4 against normal blind 4.7 (magnitude of "-( wall + 0.2 mm )")
sketch "A Facet 315 Triangle 4" plane through (0, 53.033, -53.033) normal (0, 0.7071, -0.7071) x axis (1, 0, 0)
  line L1 (124, 27.066) -> (61.9093, -27.066)
  line L2 (124, -27.066) -> (124, 27.066)
  line L3 (61.9093, -27.066) -> (124, -27.066)
  line L4 (120, 18.272) -> (72.5843, -23.066)
  line L5 (120, -23.066) -> (120, 18.272)
  line L6 (72.5843, -23.066) -> (120, -23.066)
  point P1 (0, 0)
  point P2 (61.9093, -27.066)
  point P3 (124, 27.066)
  point P4 (124, -27.066)
  dimension "d321" distance P1 P2 = 61.9093 (= "Linear Dimension-2")
  dimension "d322" distance P1 P2 = 27.066 (= "Linear Dimension-3")
  dimension "d323" distance P1 P3 = 124 (= "Linear Dimension-4")
  dimension "d324" distance P1 P3 = 27.066 (= "Linear Dimension-5")
  dimension "d325" distance P1 P4 = 124 (= "Linear Dimension-6")
  dimension "d326" distance P1 P4 = 27.066 (= "Linear Dimension-7")
  dimension "d327" = 4 (= "memberWidth / 2")
extrude "Extrude24" cut sketch "A Facet 315 Triangle 4" profile of L5 L6 L4 against normal blind 4.7 (magnitude of "-( wall + 0.2 mm )")
fillet "Fillet8" radius 1.5 (= "apertureRadius")
work_plane "WorkPlane1" RotateAngle -90 ExtraOffset 0
work_plane "WorkPlane2" AlongDistance 75 (= "bodyWidth / 2") ExtraOffset 0
sketch "B Facet 0 Triangle 1" plane through (0, 75, 0) normal (0, 1, 0) x axis (1, 0, 0)
  line L1 (-84.8995, -27.066) -> (-84.8995, 27.066)
  line L2 (-124, 27.066) -> (-84.8995, -27.066)
  line L3 (-84.8995, 27.066) -> (-124, 27.066)
  line L4 (-88.8995, -14.697) -> (-88.8995, 23.066)
  line L5 (-116.1764, 23.066) -> (-88.8995, -14.697)
  line L6 (-88.8995, 23.066) -> (-116.1764, 23.066)
  point P1 (0, 0)
  point P2 (-84.8995, 27.066)
  point P3 (-84.8995, -27.066)
  point P4 (-124, 27.066)
  dimension "d336" distance P1 P2 = 84.8995 (= "Linear Dimension-2")
  dimension "d337" distance P1 P2 = 27.066 (= "Linear Dimension-3")
  dimension "d338" distance P1 P3 = 84.8995 (= "Linear Dimension-4")
  dimension "d339" distance P1 P3 = 27.066 (= "Linear Dimension-5")
  dimension "d340" distance P1 P4 = 124 (= "Linear Dimension-6")
  dimension "d341" distance P1 P4 = 27.066 (= "Linear Dimension-7")
  dimension "d342" = 4 (= "memberWidth / 2")
extrude "Extrude1" cut sketch "B Facet 0 Triangle 1" profile of L5 L6 L4 against normal blind 4.7 (magnitude of "-( wall + 0.2 mm )")
sketch "B Facet 0 Triangle 2" plane through (0, 75, 0) normal (0, 1, 0) x axis (1, 0, 0)
  line L1 (-124, 27.066) -> (-84.8995, -27.066)
  line L2 (-124, -27.066) -> (-124, 27.066)
  line L3 (-84.8995, -27.066) -> (-124, -27.066)
  line L4 (-120, 14.697) -> (-92.7231, -23.066)
  line L5 (-120, -23.066) -> (-120, 14.697)
  line L6 (-92.7231, -23.066) -> (-120, -23.066)
  point P1 (0, 0)
  point P2 (-84.8995, -27.066)
  point P3 (-124, 27.066)
  point P4 (-124, -27.066)
  dimension "d345" distance P1 P2 = 84.8995 (= "Linear Dimension-2")
  dimension "d346" distance P1 P2 = 27.066 (= "Linear Dimension-3")
  dimension "d347" distance P1 P3 = 124 (= "Linear Dimension-4")
  dimension "d348" distance P1 P3 = 27.066 (= "Linear Dimension-5")
  dimension "d349" distance P1 P4 = 124 (= "Linear Dimension-6")
  dimension "d350" distance P1 P4 = 27.066 (= "Linear Dimension-7")
  dimension "d351" = -4 (= "-memberWidth / 2")
extrude "Extrude2" cut sketch "B Facet 0 Triangle 2" profile of L5 L6 L4 against normal blind 4.7 (magnitude of "-( wall + 0.2 mm )")
fillet "Fillet1" radius 1.5 (= "apertureRadius")
work_plane "WorkPlane3" RotateAngle -45 ExtraOffset 0
work_plane "WorkPlane4" AlongDistance 75 (= "bodyWidth / 2") ExtraOffset 0
sketch "B Facet 45 Triangle 1" plane through (0, 53.033, 53.033) normal (0, 0.7071, 0.7071) x axis (1, 0, 0)
  line L1 (-43.7939, -27.066) -> (-82.0711, 27.066)
  line L2 (-124, 27.066) -> (-43.7939, -27.066)
  line L3 (-82.0711, 27.066) -> (-124, 27.066)
  line L4 (-59.6927, -11.51) -> (-84.1416, 23.066)
  line L5 (-110.9231, 23.066) -> (-59.6927, -11.51)
  line L6 (-84.1416, 23.066) -> (-110.9231, 23.066)
  point P1 (0, 0)
  point P2 (-82.0711, 27.066)
  point P3 (-43.7939, -27.066)
  point P4 (-124, 27.066)
  dimension "d360" distance P1 P2 = 82.0711 (= "Linear Dimension-2")
  dimension "d361" distance P1 P2 = 27.066 (= "Linear Dimension-3")
  dimension "d362" distance P1 P3 = 43.7939 (= "Linear Dimension-4")
  dimension "d363" distance P1 P3 = 27.066 (= "Linear Dimension-5")
  dimension "d364" distance P1 P4 = 124 (= "Linear Dimension-6")
  dimension "d365" distance P1 P4 = 27.066 (= "Linear Dimension-7")
  dimension "d366" = 4 (= "memberWidth / 2")
extrude "Extrude3" cut sketch "B Facet 45 Triangle 1" profile of L5 L6 L4 against normal blind 4.7 (magnitude of "-( wall + 0.2 mm )")
sketch "B Facet 45 Triangle 2" plane through (0, 53.033, 53.033) normal (0, 0.7071, 0.7071) x axis (1, 0, 0)
  line L1 (-124, 27.066) -> (-43.7939, -27.066)
  line L2 (-124, -27.066) -> (-124, 27.066)
  line L3 (-43.7939, -27.066) -> (-124, -27.066)
  line L4 (-120, 19.5406) -> (-56.8709, -23.066)
  line L5 (-120, -23.066) -> (-120, 19.5406)
  line L6 (-56.8709, -23.066) -> (-120, -23.066)
  point P1 (0, 0)
  point P2 (-43.7939, -27.066)
  point P3 (-124, 27.066)
  point P4 (-124, -27.066)
  dimension "d369" distance P1 P2 = 43.7939 (= "Linear Dimension-2")
  dimension "d370" distance P1 P2 = 27.066 (= "Linear Dimension-3")
  dimension "d371" distance P1 P3 = 124 (= "Linear Dimension-4")
  dimension "d372" distance P1 P3 = 27.066 (= "Linear Dimension-5")
  dimension "d373" distance P1 P4 = 124 (= "Linear Dimension-6")
  dimension "d374" distance P1 P4 = 27.066 (= "Linear Dimension-7")
  dimension "d375" = -4 (= "-memberWidth / 2")
extrude "Extrude4" cut sketch "B Facet 45 Triangle 2" profile of L5 L6 L4 against normal blind 4.7 (magnitude of "-( wall + 0.2 mm )")
fillet "Fillet2" radius 1.5 (= "apertureRadius")
work_plane "WorkPlane5" RotateAngle 0 ExtraOffset 0
work_plane "WorkPlane6" AlongDistance 75 (= "bodyWidth / 2") ExtraOffset 0
sketch "B Facet 90 Triangle 1" plane through (0, 0, 75) normal (0, 0, 1) x axis (1, 0, 0)
  line L1 (-36.9655, 27.066) -> (17.1665, -27.066)
  line L2 (-53.4167, -27.066) -> (-36.9655, 27.066)
  line L3 (17.1665, -27.066) -> (-53.4167, -27.066)
  line L4 (-35.0777, 19.5214) -> (7.5097, -23.066)
  line L5 (-48.0205, -23.066) -> (-35.0777, 19.5214)
  line L6 (7.5097, -23.066) -> (-48.0205, -23.066)
  point P1 (0, 0)
  point P2 (17.1665, -27.066)
  point P3 (-36.9655, 27.066)
  point P4 (-53.4167, -27.066)
  dimension "d384" distance P1 P2 = 17.1665 (= "Linear Dimension-2")
  dimension "d385" distance P1 P2 = 27.066 (= "Linear Dimension-3")
  dimension "d386" distance P1 P3 = 36.9655 (= "Linear Dimension-4")
  dimension "d387" distance P1 P3 = 27.066 (= "Linear Dimension-5")
  dimension "d388" distance P1 P4 = 53.4167 (= "Linear Dimension-6")
  dimension "d389" distance P1 P4 = 27.066 (= "Linear Dimension-7")
  dimension "d390" = -4 (= "-memberWidth / 2")
extrude "Extrude5" cut sketch "B Facet 90 Triangle 1" profile of L5 L6 L4 against normal blind 4.7 (magnitude of "-( wall + 0.2 mm )")
sketch "B Facet 90 Triangle 2" plane through (0, 0, 75) normal (0, 0, 1) x axis (1, 0, 0)
  line L1 (-53.4167, -27.066) -> (-36.9655, 27.066)
  line L2 (-124, 27.066) -> (-53.4167, -27.066)
  line L3 (-36.9655, 27.066) -> (-124, 27.066)
  line L4 (-55.5648, -20.3777) -> (-42.3618, 23.066)
  line L5 (-112.2115, 23.066) -> (-55.5648, -20.3777)
  line L6 (-42.3618, 23.066) -> (-112.2115, 23.066)
  point P1 (0, 0)
  point P2 (-36.9655, 27.066)
  point P3 (-53.4167, -27.066)
  point P4 (-124, 27.066)
  dimension "d393" distance P1 P2 = 36.9655 (= "Linear Dimension-2")
  dimension "d394" distance P1 P2 = 27.066 (= "Linear Dimension-3")
  dimension "d395" distance P1 P3 = 53.4167 (= "Linear Dimension-4")
  dimension "d396" distance P1 P3 = 27.066 (= "Linear Dimension-5")
  dimension "d397" distance P1 P4 = 124 (= "Linear Dimension-6")
  dimension "d398" distance P1 P4 = 27.066 (= "Linear Dimension-7")
  dimension "d399" = 4 (= "memberWidth / 2")
extrude "Extrude6" cut sketch "B Facet 90 Triangle 2" profile of L5 L6 L4 against normal blind 4.7 (magnitude of "-( wall + 0.2 mm )")
sketch "B Facet 90 Triangle 3" plane through (0, 0, 75) normal (0, 0, 1) x axis (1, 0, 0)
  line L1 (-124, 27.066) -> (-53.4167, -27.066)
  line L2 (-124, -27.066) -> (-124, 27.066)
  line L3 (-53.4167, -27.066) -> (-124, -27.066)
  line L4 (-120, 18.9574) -> (-65.2053, -23.066)
  line L5 (-120, -23.066) -> (-120, 18.9574)
  line L6 (-65.2053, -23.066) -> (-120, -23.066)
  point P1 (0, 0)
  point P2 (-53.4167, -27.066)
  point P3 (-124, 27.066)
  point P4 (-124, -27.066)
  dimension "d402" distance P1 P2 = 53.4167 (= "Linear Dimension-2")
  dimension "d403" distance P1 P2 = 27.066 (= "Linear Dimension-3")
  dimension "d404" distance P1 P3 = 124 (= "Linear Dimension-4")
  dimension "d405" distance P1 P3 = 27.066 (= "Linear Dimension-5")
  dimension "d406" distance P1 P4 = 124 (= "Linear Dimension-6")
  dimension "d407" distance P1 P4 = 27.066 (= "Linear Dimension-7")
  dimension "d408" = -4 (= "-memberWidth / 2")
extrude "Extrude7" cut sketch "B Facet 90 Triangle 3" profile of L5 L6 L4 against normal blind 4.7 (magnitude of "-( wall + 0.2 mm )")
fillet "Fillet3" radius 1.5 (= "apertureRadius")
work_plane "WorkPlane7" RotateAngle 45 ExtraOffset 0
work_plane "WorkPlane8" AlongDistance 75 (= "bodyWidth / 2") ExtraOffset 0
sketch "B Facet 135 Triangle 1" plane through (0, -53.033, 53.033) normal (0, -0.7071, 0.7071) x axis (1, 0, 0)
  line L1 (62.2721, -27.066) -> (23.9949, 27.066)
  line L2 (-25.3367, 27.066) -> (62.2721, -27.066)
  line L3 (23.9949, 27.066) -> (-25.3367, 27.066)
  line L4 (47.6674, -13.34) -> (21.9244, 23.066)
  line L5 (-11.2532, 23.066) -> (47.6674, -13.34)
  line L6 (21.9244, 23.066) -> (-11.2532, 23.066)
  point P1 (0, 0)
  point P2 (23.9949, 27.066)
  point P3 (62.2721, -27.066)
  point P4 (-25.3367, 27.066)
  dimension "d417" distance P1 P2 = 23.9949 (= "Linear Dimension-2")
  dimension "d418" distance P1 P2 = 27.066 (= "Linear Dimension-3")
  dimension "d419" distance P1 P3 = 62.2721 (= "Linear Dimension-4")
  dimension "d420" distance P1 P3 = 27.066 (= "Linear Dimension-5")
  dimension "d421" distance P1 P4 = 25.3367 (= "Linear Dimension-6")
  dimension "d422" distance P1 P4 = 27.066 (= "Linear Dimension-7")
  dimension "d423" = 4 (= "memberWidth / 2")
extrude "Extrude8" cut sketch "B Facet 135 Triangle 1" profile of L5 L6 L4 against normal blind 4.7 (magnitude of "-( wall + 0.2 mm )")
sketch "B Facet 135 Triangle 2" plane through (0, -53.033, 53.033) normal (0, -0.7071, 0.7071) x axis (1, 0, 0)
  line L1 (-25.3367, 27.066) -> (62.2721, -27.066)
  line L2 (-61.9093, -27.066) -> (-25.3367, 27.066)
  line L3 (62.2721, -27.066) -> (-61.9093, -27.066)
  line L4 (-24.1722, 21.6445) -> (48.1886, -23.066)
  line L5 (-54.3795, -23.066) -> (-24.1722, 21.6445)
  line L6 (48.1886, -23.066) -> (-54.3795, -23.066)
  point P1 (0, 0)
  point P2 (62.2721, -27.066)
  point P3 (-25.3367, 27.066)
  point P4 (-61.9093, -27.066)
  dimension "d426" distance P1 P2 = 62.2721 (= "Linear Dimension-2")
  dimension "d427" distance P1 P2 = 27.066 (= "Linear Dimension-3")
  dimension "d428" distance P1 P3 = 25.3367 (= "Linear Dimension-4")
  dimension "d429" distance P1 P3 = 27.066 (= "Linear Dimension-5")
  dimension "d430" distance P1 P4 = 61.9093 (= "Linear Dimension-6")
  dimension "d431" distance P1 P4 = 27.066 (= "Linear Dimension-7")
  dimension "d432" = -4 (= "-memberWidth / 2")
extrude "Extrude9" cut sketch "B Facet 135 Triangle 2" profile of L5 L6 L4 against normal blind 4.7 (magnitude of "-( wall + 0.2 mm )")
sketch "B Facet 135 Triangle 3" plane through (0, -53.033, 53.033) normal (0, -0.7071, 0.7071) x axis (1, 0, 0)
  line L1 (-61.9093, -27.066) -> (-25.3367, 27.066)
  line L2 (-124, 27.066) -> (-61.9093, -27.066)
  line L3 (-25.3367, 27.066) -> (-124, 27.066)
  line L4 (-62.6909, -21.0779) -> (-32.8665, 23.066)
  line L5 (-113.325, 23.066) -> (-62.6909, -21.0779)
  line L6 (-32.8665, 23.066) -> (-113.325, 23.066)
  point P1 (0, 0)
  point P2 (-25.3367, 27.066)
  point P3 (-61.9093, -27.066)
  point P4 (-124, 27.066)
  dimension "d435" distance P1 P2 = 25.3367 (= "Linear Dimension-2")
  dimension "d436" distance P1 P2 = 27.066 (= "Linear Dimension-3")
  dimension "d437" distance P1 P3 = 61.9093 (= "Linear Dimension-4")
  dimension "d438" distance P1 P3 = 27.066 (= "Linear Dimension-5")
  dimension "d439" distance P1 P4 = 124 (= "Linear Dimension-6")
  dimension "d440" distance P1 P4 = 27.066 (= "Linear Dimension-7")
  dimension "d441" = 4 (= "memberWidth / 2")
extrude "Extrude10" cut sketch "B Facet 135 Triangle 3" profile of L5 L6 L4 against normal blind 4.7 (magnitude of "-( wall + 0.2 mm )")
sketch "B Facet 135 Triangle 4" plane through (0, -53.033, 53.033) normal (0, -0.7071, 0.7071) x axis (1, 0, 0)
  line L1 (-124, 27.066) -> (-61.9093, -27.066)
  line L2 (-124, -27.066) -> (-124, 27.066)
  line L3 (-61.9093, -27.066) -> (-124, -27.066)
  line L4 (-120, 18.272) -> (-72.5843, -23.066)
  line L5 (-120, -23.066) -> (-120, 18.272)
  line L6 (-72.5843, -23.066) -> (-120, -23.066)
  point P1 (0, 0)
  point P2 (-61.9093, -27.066)
  point P3 (-124, 27.066)
  point P4 (-124, -27.066)
  dimension "d444" distance P1 P2 = 61.9093 (= "Linear Dimension-2")
  dimension "d445" distance P1 P2 = 27.066 (= "Linear Dimension-3")
  dimension "d446" distance P1 P3 = 124 (= "Linear Dimension-4")
  dimension "d447" distance P1 P3 = 27.066 (= "Linear Dimension-5")
  dimension "d448" distance P1 P4 = 124 (= "Linear Dimension-6")
  dimension "d449" distance P1 P4 = 27.066 (= "Linear Dimension-7")
  dimension "d450" = -4 (= "-memberWidth / 2")
extrude "Extrude11" cut sketch "B Facet 135 Triangle 4" profile of L5 L6 L4 against normal blind 4.7 (magnitude of "-( wall + 0.2 mm )")
fillet "Fillet4" radius 1.5 (= "apertureRadius")
work_plane "WorkPlane9" RotateAngle 90 ExtraOffset 0
work_plane "WorkPlane10" AlongDistance 75 (= "bodyWidth / 2") ExtraOffset 0
sketch "B Facet 180 Triangle 1" plane through (0, -75, 0) normal (0, -1, 0) x axis (-1, 0, 0)
  line L1 (-65.1005, 27.066) -> (-65.1005, -27.066)
  line L2 (-2.067, -27.066) -> (-65.1005, 27.066)
  line L3 (-65.1005, -27.066) -> (-2.067, -27.066)
  line L4 (-61.1005, 18.3583) -> (-61.1005, -23.066)
  line L5 (-12.8644, -23.066) -> (-61.1005, 18.3583)
  line L6 (-61.1005, -23.066) -> (-12.8644, -23.066)
  point P1 (0, 0)
  point P2 (-65.1005, -27.066)
  point P3 (-65.1005, 27.066)
  point P4 (-2.067, -27.066)
  dimension "d459" distance P1 P2 = 65.1005 (= "Linear Dimension-2")
  dimension "d460" distance P1 P2 = 27.066 (= "Linear Dimension-3")
  dimension "d461" distance P1 P3 = 65.1005 (= "Linear Dimension-4")
  dimension "d462" distance P1 P3 = 27.066 (= "Linear Dimension-5")
  dimension "d463" distance P1 P4 = 2.067 (= "Linear Dimension-6")
  dimension "d464" distance P1 P4 = 27.066 (= "Linear Dimension-7")
  dimension "d465" = 4 (= "memberWidth / 2")
extrude "Extrude12" cut sketch "B Facet 180 Triangle 1" profile of L5 L6 L4 against normal blind 4.7 (magnitude of "-( wall + 0.2 mm )")
sketch "B Facet 180 Triangle 2" plane through (0, -75, 0) normal (0, -1, 0) x axis (-1, 0, 0)
  line L1 (-2.067, -27.066) -> (-65.1005, 27.066)
  line L2 (60.9665, 27.066) -> (-2.067, -27.066)
  line L3 (-65.1005, 27.066) -> (60.9665, 27.066)
  line L4 (-2.067, -21.7934) -> (-54.3031, 23.066)
  line L5 (50.1691, 23.066) -> (-2.067, -21.7934)
  line L6 (-54.3031, 23.066) -> (50.1691, 23.066)
  point P1 (0, 0)
  point P2 (-65.1005, 27.066)
  point P3 (-2.067, -27.066)
  point P4 (60.9665, 27.066)
  dimension "d468" distance P1 P2 = 65.1005 (= "Linear Dimension-2")
  dimension "d469" distance P1 P2 = 27.066 (= "Linear Dimension-3")
  dimension "d470" distance P1 P3 = 2.067 (= "Linear Dimension-4")
  dimension "d471" distance P1 P3 = 27.066 (= "Linear Dimension-5")
  dimension "d472" distance P1 P4 = 60.9665 (= "Linear Dimension-6")
  dimension "d473" distance P1 P4 = 27.066 (= "Linear Dimension-7")
  dimension "d474" = -4 (= "-memberWidth / 2")
extrude "Extrude13" cut sketch "B Facet 180 Triangle 2" profile of L5 L6 L4 against normal blind 4.7 (magnitude of "-( wall + 0.2 mm )")
sketch "B Facet 180 Triangle 3" plane through (0, -75, 0) normal (0, -1, 0) x axis (-1, 0, 0)
  line L1 (60.9665, 27.066) -> (-2.067, -27.066)
  line L2 (124, -27.066) -> (60.9665, 27.066)
  line L3 (-2.067, -27.066) -> (124, -27.066)
  line L4 (60.9665, 21.7934) -> (8.7304, -23.066)
  line L5 (113.2026, -23.066) -> (60.9665, 21.7934)
  line L6 (8.7304, -23.066) -> (113.2026, -23.066)
  point P1 (0, 0)
  point P2 (-2.067, -27.066)
  point P3 (60.9665, 27.066)
  point P4 (124, -27.066)
  dimension "d477" distance P1 P2 = 2.067 (= "Linear Dimension-2")
  dimension "d478" distance P1 P2 = 27.066 (= "Linear Dimension-3")
  dimension "d479" distance P1 P3 = 60.9665 (= "Linear Dimension-4")
  dimension "d480" distance P1 P3 = 27.066 (= "Linear Dimension-5")
  dimension "d481" distance P1 P4 = 124 (= "Linear Dimension-6")
  dimension "d482" distance P1 P4 = 27.066 (= "Linear Dimension-7")
  dimension "d483" = 4 (= "memberWidth / 2")
extrude "Extrude14" cut sketch "B Facet 180 Triangle 3" profile of L5 L6 L4 against normal blind 4.7 (magnitude of "-( wall + 0.2 mm )")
